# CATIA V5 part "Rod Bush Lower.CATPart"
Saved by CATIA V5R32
Part number: Rod Nush Lower
Bounding box of the stored display mesh (mm): x -7.5 to 7.5, y -7.312 to 7.312, z -12 to 12
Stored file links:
  D:\PROJECTS\Project 2022\CATIA V5 6R 2022\Resources\Part Files\c13_catia_v5_6r2022_prt\c13_catia_v5-6r2022_figr_13-41\Part & Asm files\Rod Bush Lower.CATPart
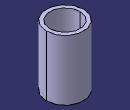
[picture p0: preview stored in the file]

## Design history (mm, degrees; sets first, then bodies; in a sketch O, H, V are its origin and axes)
Body1 (main body)
  Sketch1 on xy-plane, origin (0, 0, 0), H (1, 0, 0), V (0, 1, 0)
    circle A1 centre (0, 0) radius 6
    circle A2 centre (0, 0) radius 7.5
    point P1 (0, 0)
    radius A2 = 7.5
    radius A1 = 6
    coincidence: P1 H
    concentricity: A1 A2
  Pad1: profile Sketch1, direction (0, 0, 1), length 12, mirrored extent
